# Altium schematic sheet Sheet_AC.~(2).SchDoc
size A4
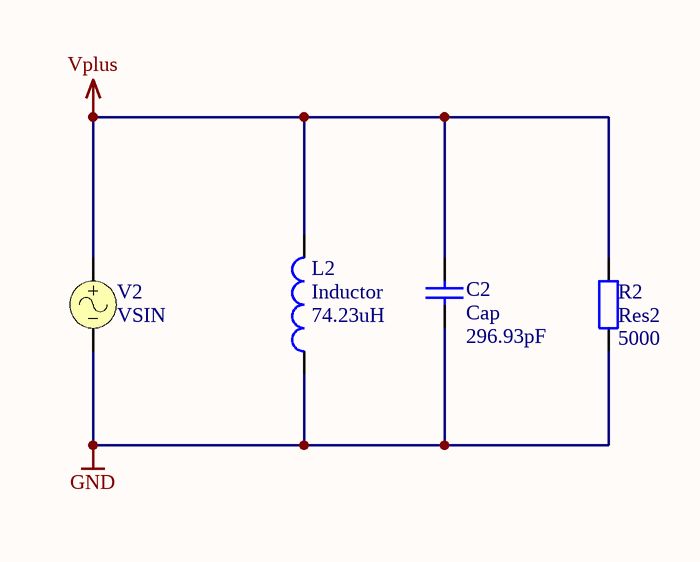
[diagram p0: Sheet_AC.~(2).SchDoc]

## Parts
C2  Cap  value 296.93pF  [RAD-0.3]
L2  Inductor  value 74.23uH  [0402-A]
R2  Res2  value 5000  [AXIAL-0.4]
V2  VSIN

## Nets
GND: C2.1 L2.1 R2.1 V2.2
Vplus: C2.2 L2.2 R2.2 V2.1

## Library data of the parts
C2 = Cap: Capacitor
L2 = Inductor: Code_IEC: 1005
R2 = Res2: Resistor
V2 = VSIN: Sinusoidal Voltage Source; Note: PCB Footprint - Not required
